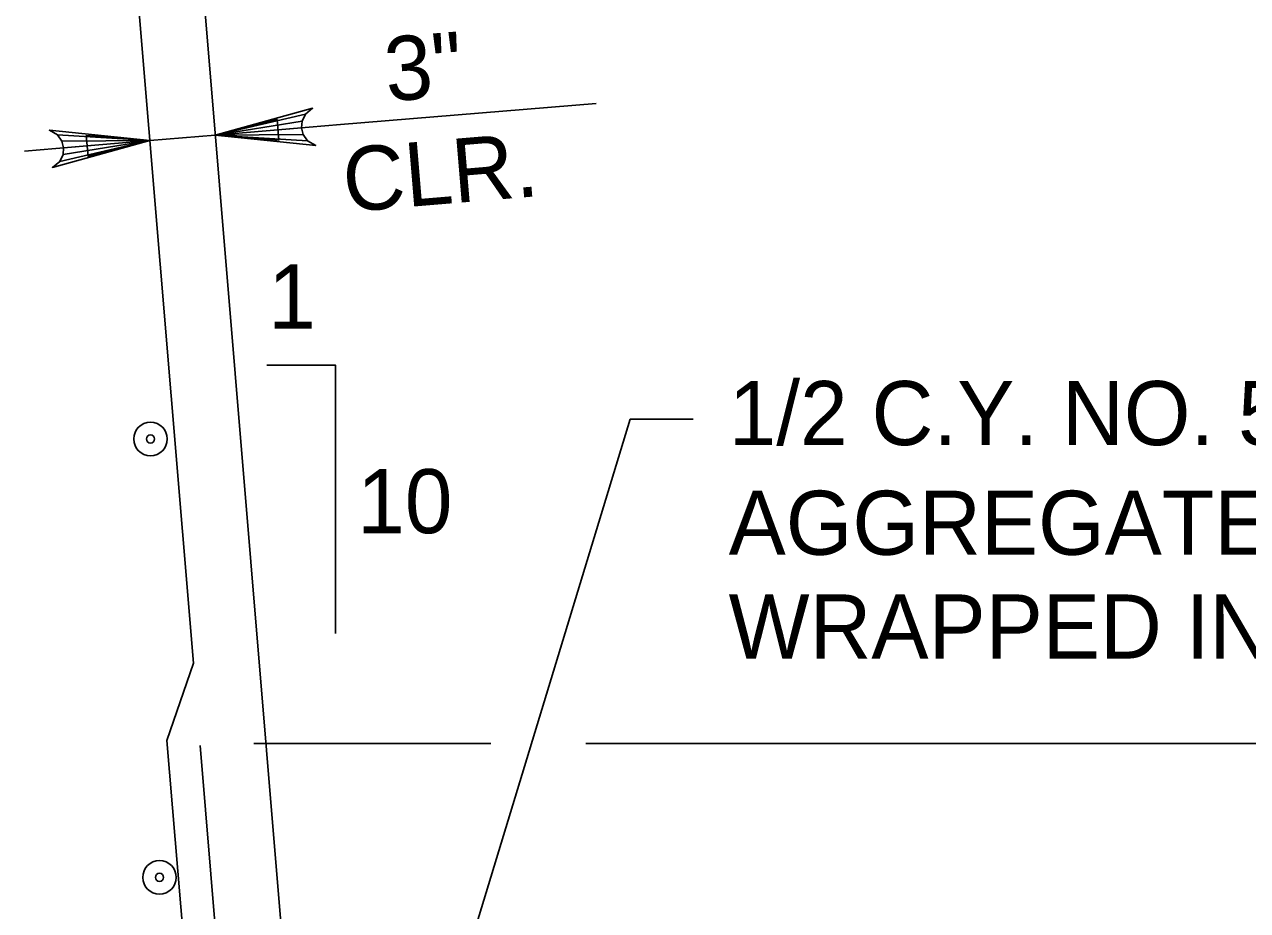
# Model space of a CAD drawing. Extents: x 638340 to 640242, y 295465 to 298435.
# Drawn here: x 639123.1 to 639180.4, y 298289.7 to 298331.2 of the extents above; entities that cross this region are included whole.
import ezdxf

# ---------------------------------------------------------------- set-up
doc = ezdxf.new("R2010")
doc.units = 0
for name, color, linetype in [('3', 7, 'Continuous'), ('Level 3', 7, 'Continuous'), ('Level 5', 7, 'Continuous'), ('Level 9', 7, 'Continuous')]:
    doc.layers.add(name, color=color, linetype=linetype)

# ---------------------------------------------------------------- blocks, each defined once
blk = doc.blocks.new('B')
at = {"layer": '3'}
blk.add_circle((0, 0), 0.16, dxfattribs=at)
for start, end in [(0, 180), (180, 0)]:
    blk.add_arc((0, 0), 0.0391, start, end, dxfattribs=at)

msp = doc.modelspace()

# ---------------------------------------------------------------- linework, layer by layer
at = {"layer": 'Level 3'}
for p, q in [((639137.919, 298326.492), (639149.88, 298327.487)), ((639132.045, 298326.001), (639137.919, 298326.492)), ((639128.986, 298325.747), (639123.112, 298325.256)), ((639128.986, 298325.747), (639132.045, 298326.001)), ((639142.311, 298282.609), (639151.481, 298312.707)), ((639151.481, 298312.707), (639154.427, 298312.707)), ((639133.855, 298297.527), (639144.955, 298297.527)), ((639149.402, 298297.527), (639185.933, 298297.527))]:
    msp.add_line(p, q, dxfattribs=at)
for points in [[(639132.045, 298326.001), (639136.607, 298327.257), (639136.27, 298326.98), (639136.112, 298326.654), (639136.085, 298326.338), (639136.164, 298326.032), (639136.374, 298325.737), (639136.753, 298325.518), (639132.045, 298326.001), (639136.374, 298325.737), (639136.164, 298326.032), (639132.045, 298326.001), (639136.085, 298326.338), (639136.112, 298326.654), (639132.045, 298326.001), (639136.27, 298326.98)], [(639128.986, 298325.747), (639124.424, 298324.491), (639124.761, 298324.768), (639124.919, 298325.094), (639124.946, 298325.41), (639124.867, 298325.716), (639124.657, 298326.011), (639124.279, 298326.23), (639128.986, 298325.747), (639124.657, 298326.011), (639124.867, 298325.716), (639128.986, 298325.747), (639124.946, 298325.41), (639124.919, 298325.094), (639128.986, 298325.747), (639124.761, 298324.768)]]:
    msp.add_lwpolyline(points, dxfattribs=at)
for points in [[(639134.942, 298326.735), (639135.023, 298325.758), (639132.045, 298326.001)], [(639126.009, 298325.99), (639126.09, 298325.013), (639128.986, 298325.747)]]:
    msp.add_lwpolyline(points, close=True, dxfattribs=at)
at = {"layer": 'Level 5'}
for p, q in [((639127.425, 298344.482), (639131.024, 298301.286)), ((639129.785, 298297.669), (639131.024, 298301.286)), ((639129.785, 298297.669), (639131.648, 298275.312)), ((639131.344, 298297.437), (639133.178, 298275.441))]:
    msp.add_line(p, q, dxfattribs=at)
at = {"layer": 'Level 9'}
msp.add_line((639128.903, 298363.704), (639140.3, 298226.948), dxfattribs=at)
msp.add_lwpolyline([(639134.455, 298315.228), (639137.68, 298315.228), (639137.68, 298302.668)], dxfattribs=at)

# ---------------------------------------------------------------- block references
at = {"layer": 'Level 3', "xscale": 4.911876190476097, "yscale": 4.911876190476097, "rotation": 90}
for p in [(639129.015, 298311.778), (639129.435, 298291.259)]:
    msp.add_blockref('B', p, dxfattribs=at)

# ---------------------------------------------------------------- texts
at = {"layer": 'Level 3'}
for s, p in [('3"', (639140.1, 298327.569)), ('CLR.', (639138.149, 298322.393))]:
    msp.add_text(s, height=3.0001, rotation=4.7636, dxfattribs=at).set_placement(p)
for s, height, p in [('1', 3, (639134.524, 298316.947)), ('1/2 C.Y. NO. 57 COARSE', 3.00014, (639156.089, 298311.491)), ('10', 3.0001, (639138.693, 298307.368)), ('AGGREGATE @ EACH WEEPHOLE', 3.00014, (639156.089, 298306.357)), ('WRAPPED IN CLASS 1 GEOTEXTILE', 3.00014, (639156.089, 298301.502))]:
    msp.add_text(s, height=height, dxfattribs=at).set_placement(p)

doc.saveas('drawing.dxf')
